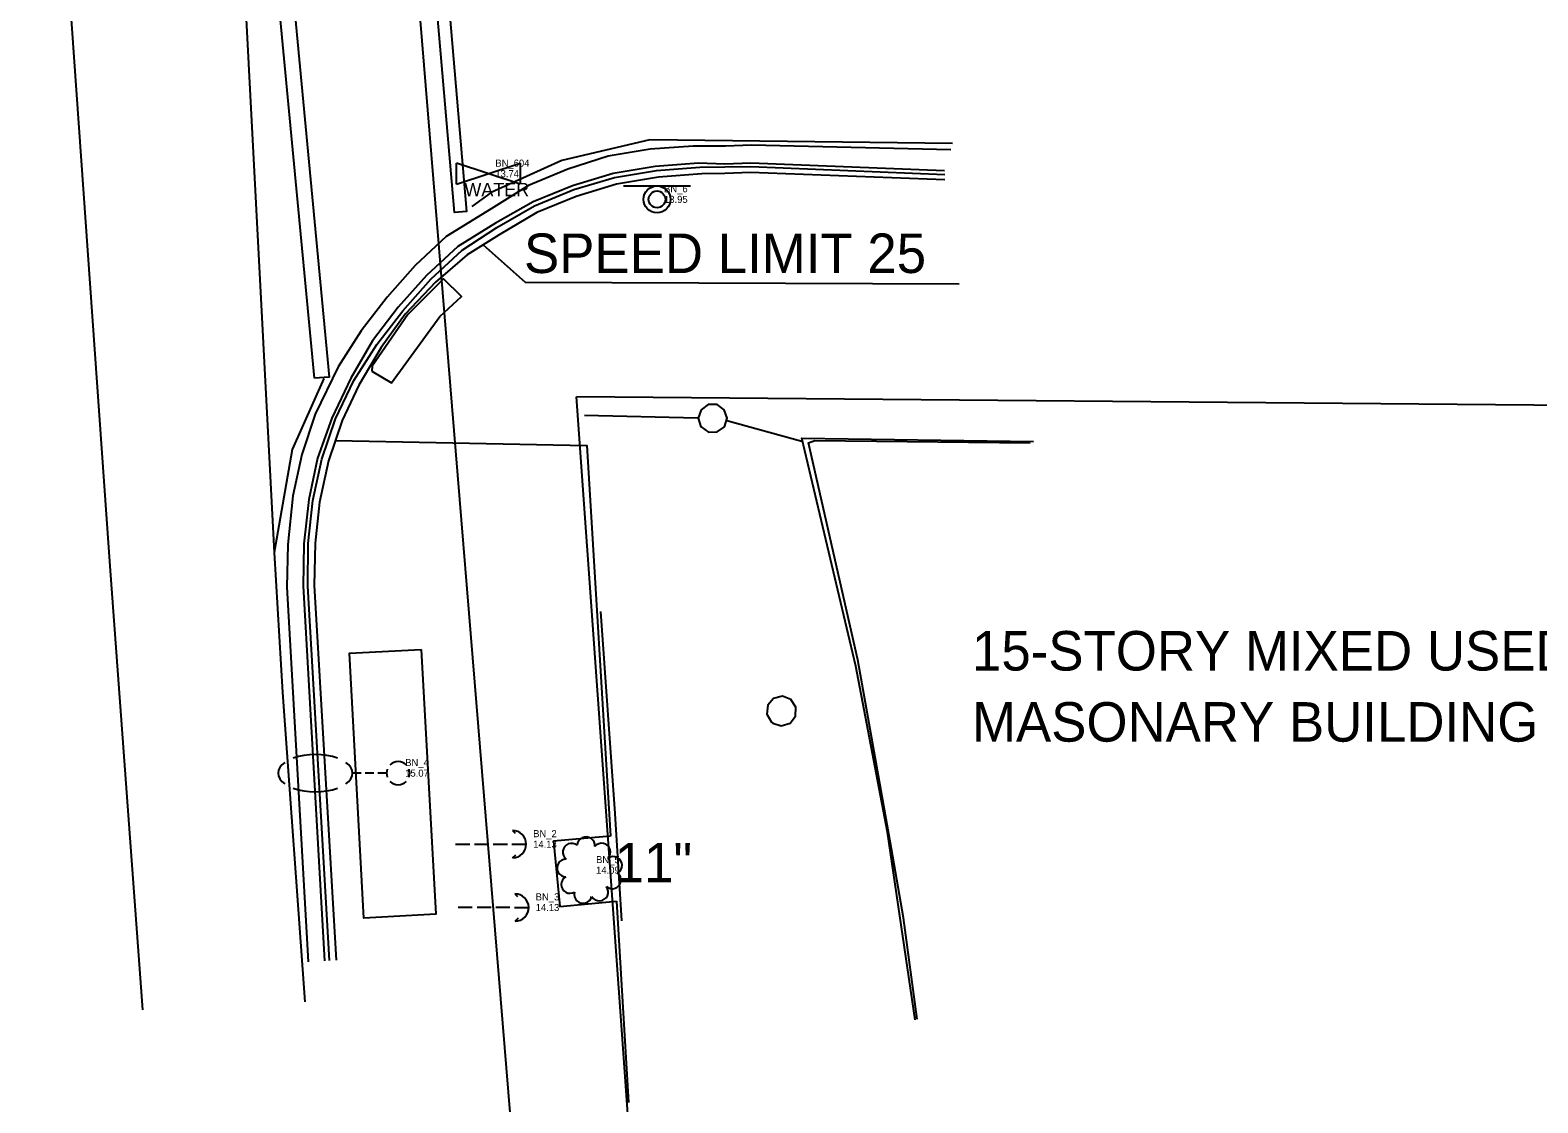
# Model space of a CAD drawing. Extents: x 509744 to 512285, y 1314862 to 1316822.
# Drawn here: x 511244.1 to 511351, y 1315227.3 to 1315303.3 of the extents above; entities that cross this region are included whole.
import ezdxf

# ---------------------------------------------------------------- set-up
doc = ezdxf.new("R2010")
doc.units = 0
for name, color, linetype in [('Building_ep', 7, 'Continuous'), ('CGBack_ep', 7, 'Continuous'), ('CGep_ep', 7, 'Continuous'), ('CGFace_ep', 7, 'Continuous'), ('CurbRampWarning_ep', 7, 'Continuous'), ('GuyWireAnchor_ep', 7, 'Continuous'), ('LaneLine_ep', 7, 'Continuous'), ('Luminaire_ep', 7, 'Continuous'), ('PavtAsphalt_ep', 7, 'Continuous'), ('PavtBreak_ep', 7, 'Continuous'), ('PavtBrick_ep', 7, 'Continuous'), ('PilingColumn_ep', 7, 'Continuous'), ('PipeCulvert_ep', 7, 'Continuous'), ('PMRK_ep', 7, 'Continuous'), ('Railing_ep', 7, 'Continuous'), ('RWLine_ep', 7, 'Continuous'), ('SidewalkBack_ep', 7, 'Continuous'), ('SidewalkFront_ep', 7, 'Continuous'), ('SignSingle_ep', 7, 'Continuous'), ('TextElevLabel', 7, 'Continuous'), ('TextPtLabel', 7, 'Continuous'), ('TextTopoLabel_ep', 7, 'Continuous'), ('TreeOak_ep', 7, 'Continuous'), ('ValveWater_ep', 7, 'Continuous')]:
    doc.layers.add(name, color=color, linetype=linetype)

msp = doc.modelspace()

# ---------------------------------------------------------------- linework, layer by layer
at = {"layer": 'Building_ep'}
msp.add_lwpolyline([(511307, 1315233.23), (511306.03, 1315240.41), (511305.19, 1315245.3), (511302.79, 1315258.68), (511299.31, 1315274.07), (511299.74, 1315274.23), (511315.02, 1315274.07)], dxfattribs=at)
at = {"layer": 'CGBack_ep'}
msp.add_lwpolyline([(511308.96, 1315292.7), (511295.2, 1315293.22), (511293.36, 1315293.15), (511291.73, 1315293.13), (511288.67, 1315292.9), (511285.68, 1315292.4), (511282.82, 1315291.52), (511280.03, 1315290.38), (511277.37, 1315288.81), (511275.11, 1315287.39), (511272.85, 1315285.45), (511270.71, 1315283.19), (511269.01, 1315280.83), (511267.43, 1315278.16), (511266.25, 1315275.65), (511265.27, 1315272.8), (511264.64, 1315269.87), (511264.32, 1315266.96), (511264.26, 1315263.95), (511265.82, 1315237.4)], dxfattribs=at)
at = {"layer": 'CGep_ep'}
msp.add_lwpolyline([(511308.93, 1315293.35), (511295.22, 1315293.88), (511293.38, 1315293.81), (511291.51, 1315293.88), (511288.44, 1315293.65), (511285.46, 1315293.15), (511282.58, 1315292.29), (511279.79, 1315291.15), (511277.12, 1315289.63), (511274.43, 1315287.98), (511272.22, 1315285.93), (511270.22, 1315283.69), (511268.39, 1315281.3), (511266.86, 1315278.66), (511265.51, 1315275.82), (511264.5, 1315272.98), (511263.87, 1315270.04), (511263.53, 1315266.91), (511263.47, 1315263.9), (511264.99, 1315237.35)], dxfattribs=at)
at = {"layer": 'CGFace_ep'}
msp.add_lwpolyline([(511265.34, 1315237.37), (511263.8, 1315263.92), (511263.84, 1315266.93), (511264.17, 1315269.98), (511264.81, 1315272.91), (511265.77, 1315275.76), (511267.06, 1315278.49), (511268.7, 1315281.04), (511270.53, 1315283.42), (511272.52, 1315285.66), (511274.74, 1315287.71), (511277.21, 1315289.33), (511279.88, 1315290.87), (511282.67, 1315292.01), (511285.54, 1315292.87), (511288.52, 1315293.37), (511291.59, 1315293.61), (511293.38, 1315293.63), (511295.21, 1315293.66), (511308.96, 1315293.09)], dxfattribs=at)
at = {"layer": 'CurbRampWarning_ep'}
msp.add_lwpolyline([(511268.34, 1315279.15), (511269.73, 1315278.31), (511273.17, 1315283.03), (511274.7, 1315284.44), (511273.42, 1315285.7), (511270.9, 1315283.17), (511268.37, 1315279.51)], close=True, dxfattribs=at)
at = {"layer": 'GuyWireAnchor_ep'}
for p, q in [((511278.31, 1315246.59), (511278.5, 1315246.4)), ((511274.28, 1315245.63), (511275.28, 1315245.63)), ((511275.61, 1315245.63), (511276.61, 1315245.63)), ((511276.95, 1315245.63), (511277.95, 1315245.63)), ((511278.28, 1315245.62), (511279.28, 1315245.62)), ((511278.32, 1315244.65), (511278.56, 1315244.88)), ((511278.49, 1315242.11), (511278.68, 1315241.92)), ((511274.46, 1315241.15), (511275.46, 1315241.15)), ((511275.8, 1315241.15), (511276.8, 1315241.15)), ((511277.13, 1315241.15), (511278.13, 1315241.15)), ((511278.46, 1315241.14), (511279.46, 1315241.14)), ((511278.5, 1315240.16), (511278.74, 1315240.4))]:
    msp.add_line(p, q, dxfattribs=at)
for centre in [(511278.31, 1315245.62), (511278.49, 1315241.14)]:
    msp.add_arc(centre, 0.973, 271.14, 90.0059, dxfattribs=at)
at = {"layer": 'LaneLine_ep'}
msp.add_lwpolyline([(511252.11, 1315233.88), (511249.8, 1315265.32), (511246.34, 1315314.13), (511244.12, 1315344.98)], dxfattribs=at)
at = {"layer": 'Luminaire_ep'}
for p, q in [((511267.58, 1315250.66), (511266.98, 1315250.66)), ((511268.48, 1315250.66), (511267.88, 1315250.66)), ((511269.38, 1315250.66), (511268.78, 1315250.66))]:
    msp.add_line(p, q, dxfattribs=at)
for start, end in [(45, 135), (159.9115, 200.0885), (339.9115, 20.0885), (225, 315)]:
    msp.add_arc((511270.21, 1315250.66), 0.825, start, end, dxfattribs=at)
for start_param, end_param in [(5.668326, 6.898045), (4.075781, 5.348997), (2.526733, 3.756452), (0.934187, 2.207405)]:
    msp.add_ellipse((511264.34, 1315250.66), major_axis=(-2.64, 0), ratio=0.5, start_param=start_param, end_param=end_param, dxfattribs=at)
at = {"layer": 'PavtAsphalt_ep'}
msp.add_lwpolyline([(511309.39, 1315294.84), (511295.26, 1315295.16), (511293.42, 1315295.09), (511291.13, 1315295.1), (511288.07, 1315294.87), (511285.09, 1315294.37), (511282.23, 1315293.45), (511279.44, 1315292.31), (511276.81, 1315290.65), (511273.62, 1315288.68), (511271.41, 1315286.63), (511269.42, 1315284.39), (511267.59, 1315282.01), (511265.95, 1315279.45), (511264.33, 1315276.09), (511263.37, 1315273.23), (511262.74, 1315270.3), (511262.38, 1315266.85), (511262.32, 1315263.84), (511263.84, 1315237.29)], dxfattribs=at)
at = {"layer": 'PavtBreak_ep'}
msp.add_lwpolyline([(511256.05, 1315350.05), (511259.35, 1315305.92), (511261.42, 1315266.3)], dxfattribs=at)
at = {"layer": 'PavtBrick_ep'}
msp.add_line((511285.69, 1315241.59), (511286.54, 1315227.32), dxfattribs=at)
for points in [[(511265.76, 1315274.23), (511283.58, 1315273.88), (511285.26, 1315246.2)], [(511285.26, 1315246.2), (511281.23, 1315245.83), (511281.67, 1315241.21), (511285.69, 1315241.59)]]:
    msp.add_lwpolyline(points, dxfattribs=at)
msp.add_lwpolyline([(511271.84, 1315259.43), (511272.87, 1315240.67), (511267.77, 1315240.39), (511266.75, 1315259.15)], close=True, dxfattribs=at)
at = {"layer": 'PilingColumn_ep'}
for points in [[(511291.68, 1315275.2), (511292.2, 1315274.83), (511292.83, 1315274.84), (511293.34, 1315275.21), (511293.53, 1315275.81), (511293.33, 1315276.41), (511292.82, 1315276.78), (511292.19, 1315276.78), (511291.68, 1315276.41), (511291.48, 1315275.81), (511291.67, 1315275.21)], [(511296.76, 1315254.2), (511297.37, 1315254), (511297.99, 1315254.19), (511298.38, 1315254.7), (511298.4, 1315255.34), (511298.05, 1315255.88), (511297.45, 1315256.11), (511296.83, 1315255.96), (511296.41, 1315255.47), (511296.35, 1315254.83), (511296.68, 1315254.27)]]:
    msp.add_lwpolyline(points, close=True, dxfattribs=at)
at = {"layer": 'PipeCulvert_ep'}
msp.add_line((511267.16, 1315359.89), (511284.6, 1315148.05), dxfattribs=at)
at = {"layer": 'PMRK_ep'}
for points in [[(511264.29, 1315278.64), (511259.02, 1315334.18), (511260.07, 1315334.28), (511265.33, 1315278.73)], [(511272.42, 1315321.21), (511275.06, 1315290.47), (511274.21, 1315290.4), (511271.56, 1315321.13)]]:
    msp.add_lwpolyline(points, close=True, dxfattribs=at)
for points in [[(511309.51, 1315295.27), (511288.05, 1315295.53), (511281.81, 1315294.07), (511276.81, 1315291.81), (511275.44, 1315290.81)], [(511264.95, 1315278.63), (511262.69, 1315273.59), (511261.42, 1315266.3), (511262, 1315256.38), (511263.59, 1315234.46)]]:
    msp.add_lwpolyline(points, dxfattribs=at)
at = {"layer": 'Railing_ep'}
for p, q in [((511283.42, 1315276.02), (511291.43, 1315275.83)), ((511293.52, 1315275.66), (511298.82, 1315274.18))]:
    msp.add_line(p, q, dxfattribs=at)
msp.add_lwpolyline([(511286.06, 1315240.2), (511285.6, 1315247.81), (511284.57, 1315262.11)], dxfattribs=at)
at = {"layer": 'RWLine_ep'}
for p in [(511300.26, 1315033.61), (511589.24, 1315274.63)]:
    msp.add_line(p, (511282.86, 1315277.33), dxfattribs=at)
at = {"layer": 'SidewalkBack_ep'}
msp.add_lwpolyline([(511306.87, 1315233.17), (511304.9, 1315246.47), (511302.65, 1315258.23), (511298.83, 1315274.4), (511315.26, 1315274.15)], dxfattribs=at)
at = {"layer": 'SidewalkFront_ep'}
msp.add_lwpolyline([(511276.24, 1315288.1), (511279.21, 1315285.45), (511309.97, 1315285.33)], dxfattribs=at)
at = {"layer": 'SignSingle_ep'}
msp.add_line((511286.19, 1315292.27), (511290.94, 1315292.27), dxfattribs=at)
for radius in [0.95, 0.594]:
    msp.add_circle((511288.56, 1315291.32), radius, dxfattribs=at)
at = {"layer": 'TreeOak_ep'}
for centre, radius, start, end in [((511283.53, 1315245.51), 0.629, 355.3943, 176.6549), ((511282.5, 1315245.06), 0.624, 50.7185, 233.084), ((511284.64, 1315245.06), 0.627, 315.0898, 140.6833), ((511282.1, 1315243.94), 0.625, 87.3095, 269.5618), ((511285.46, 1315244.12), 0.626, 299.4354, 127.2613), ((511282.4, 1315242.77), 0.626, 119.4469, 301.0197), ((511285.38, 1315243.09), 0.623, 229.2872, 51.2025), ((511283.32, 1315242.06), 0.625, 164.2871, 346.2767), ((511284.47, 1315242.24), 0.628, 211.1877, 36.8199)]:
    msp.add_arc(centre, radius, start, end, dxfattribs=at)
at = {"layer": 'ValveWater_ep'}
for p, q in [((511278.85, 1315292.39), (511274.35, 1315293.89)), ((511274.35, 1315292.39), (511278.85, 1315293.89)), ((511274.35, 1315292.39), (511274.35, 1315293.89)), ((511278.85, 1315293.89), (511278.85, 1315292.39))]:
    msp.add_line(p, q, dxfattribs=at)

# ---------------------------------------------------------------- texts
at = {"layer": 'TextElevLabel'}
for s, p in [('13.74', (511277.1, 1315292.89)), ('13.95', (511289.06, 1315291.07)), ('15.07', (511270.71, 1315250.41)), ('14.13', (511279.78, 1315245.37)), ('14.09', (511284.24, 1315243.53)), ('14.13', (511279.96, 1315240.89))]:
    msp.add_text(s, height=0.5, dxfattribs=at).set_placement(p)
at = {"layer": 'TextPtLabel'}
for s, p in [('BN_604', (511277.1, 1315293.64)), ('BN_6', (511289.06, 1315291.82)), ('BN_4', (511270.71, 1315251.16)), ('BN_2', (511279.78, 1315246.12)), ('BN_5', (511284.24, 1315244.28)), ('BN_3', (511279.96, 1315241.64))]:
    msp.add_text(s, height=0.5, dxfattribs=at).set_placement(p)
at = {"layer": 'TextTopoLabel_ep'}
for s, p in [('SPEED LIMIT 25', (511279.13, 1315286.1)), ('15-STORY MIXED USED', (511310.89, 1315257.93)), ('MASONARY BUILDING', (511310.89, 1315252.89)), ('11"', (511285.56, 1315242.92))]:
    msp.add_text(s, height=2.8, dxfattribs=at).set_placement(p)
at = {"layer": 'ValveWater_ep'}
msp.add_text('WATER', height=0.95, dxfattribs=at).set_placement((511274.91, 1315291.54))

doc.saveas('drawing.dxf')
